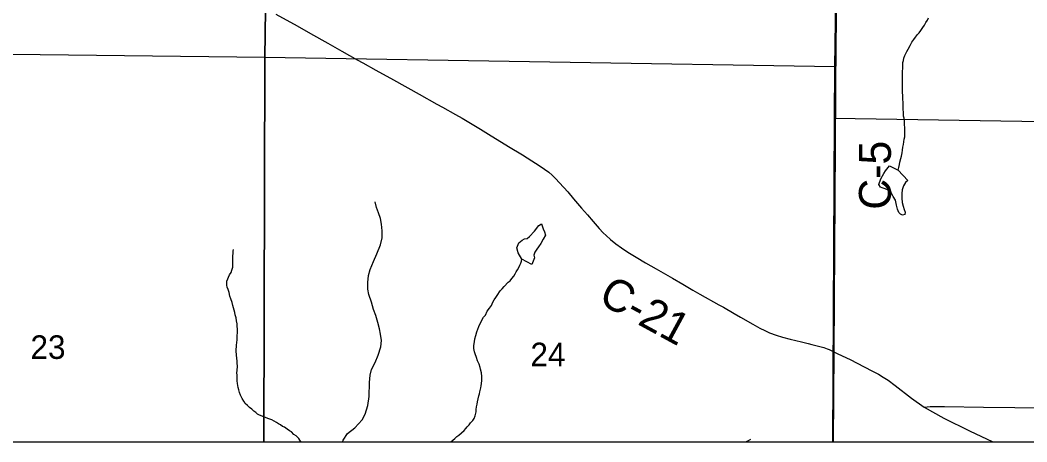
# Model space of a CAD drawing. Extents: x 0 to 34, y 0 to 22.
# Drawn here: x 26.305 to 27.199, y 13.436 to 13.811 of the extents above; entities that cross this region are included whole.
import ezdxf

# ---------------------------------------------------------------- set-up
doc = ezdxf.new("R2010")
doc.units = 0
for name, color, linetype in [('GM_X_County_Road', 7, 'Continuous'), ('GM_X_County_Road_Text', 7, 'Continuous'), ('GM_X_Minor_River', 7, 'Continuous'), ('GM_X_Section', 7, 'Continuous'), ('GM_X_Section_Text', 7, 'Continuous'), ('GM_X_Township_Road', 7, 'Continuous'), ('GM_X_Unincorporated', 7, 'Continuous'), ('SC_Scratch1', 7, 'Continuous'), ('SH_Border', 7, 'Continuous'), ('SH_Cut_Line', 7, 'Continuous')]:
    doc.layers.add(name, color=color, linetype=linetype)

msp = doc.modelspace()

# ---------------------------------------------------------------- linework, layer by layer
at = {"layer": 'GM_X_County_Road'}
for points in [[(27.02756, 13.43613), (27.02773, 13.45635), (27.02798, 13.49359), (27.02798, 13.51159), (27.0279, 13.51604), (27.02773, 13.52187), (27.02781, 13.53921), (27.02831, 13.58607), (27.02854, 13.627), (27.02896, 13.66909), (27.02939, 13.72226), (27.02962, 13.77184), (27.03013, 13.80886), (27.03053, 13.84985)], [(26.53202, 13.81591), (26.55073, 13.80543), (26.56264, 13.79873), (26.57808, 13.79005), (26.59053, 13.78305), (26.60409, 13.77547), (26.60925, 13.77261), (26.62091, 13.76611), (26.63641, 13.75753), (26.6592, 13.74482), (26.67496, 13.73609), (26.68014, 13.73326), (26.69155, 13.72694), (26.69751, 13.72357), (26.7137, 13.7137), (26.72085, 13.70932), (26.73861, 13.69847), (26.75107, 13.69086), (26.75955, 13.68567), (26.76585, 13.68165), (26.77074, 13.6783), (26.77448, 13.6755), (26.7776, 13.6729), (26.78053, 13.67008), (26.78416, 13.66622), (26.79132, 13.65804), (26.79661, 13.65194), (26.80373, 13.64372), (26.80901, 13.6376), (26.81407, 13.63173), (26.81938, 13.62567), (26.82298, 13.62184), (26.82561, 13.61923), (26.82928, 13.61591), (26.83409, 13.61203), (26.8391, 13.6084), (26.84478, 13.60463), (26.85218, 13.60007), (26.86047, 13.59518), (26.8653, 13.59237), (26.86987, 13.58972), (26.88444, 13.5814), (26.89358, 13.5761), (26.90269, 13.57076), (26.90892, 13.56728), (26.92575, 13.55793), (26.92981, 13.55564), (26.93925, 13.55023), (26.9449, 13.54697), (26.95594, 13.54062), (26.9622, 13.53721), (26.96663, 13.53499), (26.97083, 13.53305), (26.97662, 13.53088), (26.98222, 13.52913), (26.98911, 13.52732), (26.99909, 13.52496), (27.00514, 13.52353), (27.00846, 13.52271), (27.01538, 13.5209), (27.01896, 13.51979), (27.02202, 13.51867), (27.02388, 13.51798), (27.02624, 13.51688), (27.0279, 13.51604)], [(27.0279, 13.51604), (27.03143, 13.51432), (27.0423, 13.50921), (27.05493, 13.50283), (27.06238, 13.499), (27.06753, 13.49615), (27.07176, 13.49357), (27.07609, 13.49088), (27.0825, 13.48611), (27.09705, 13.47485), (27.10809, 13.46685), (27.12569, 13.45704), (27.14833, 13.44604), (27.16935, 13.43613)]]:
    msp.add_lwpolyline(points, dxfattribs=at)
at = {"layer": 'GM_X_Minor_River'}
for points in [[(27.08515, 13.67745), (27.08554, 13.6797), (27.08619, 13.68253), (27.08662, 13.68461), (27.08747, 13.68762), (27.08791, 13.68989), (27.08856, 13.69272), (27.08882, 13.69519), (27.08928, 13.69783), (27.08972, 13.70029), (27.08998, 13.70256), (27.09042, 13.70483), (27.09086, 13.70691), (27.0911, 13.71526), (27.09078, 13.71755), (27.0907, 13.72135), (27.09038, 13.72345), (27.08987, 13.72537), (27.08973, 13.72727), (27.0895, 13.7326), (27.08938, 13.73507), (27.08946, 13.73773), (27.08934, 13.7402), (27.08921, 13.74248), (27.08898, 13.74743), (27.08885, 13.74971), (27.08891, 13.7518), (27.08879, 13.75427), (27.08894, 13.75959), (27.08881, 13.76168), (27.08908, 13.77118), (27.08932, 13.77307), (27.08975, 13.77477), (27.09019, 13.77684), (27.09101, 13.7791), (27.09201, 13.78097), (27.09282, 13.78266), (27.09402, 13.78491), (27.09563, 13.78809), (27.09723, 13.79108), (27.09901, 13.79331), (27.1004, 13.79556), (27.10217, 13.79779), (27.10373, 13.79945), (27.10531, 13.8015), (27.1069, 13.80411), (27.10847, 13.80616), (27.10968, 13.8084), (27.11125, 13.81045), (27.11207, 13.81252)], [(27.07615, 13.65956), (27.07353, 13.66078), (27.0709, 13.66162), (27.06941, 13.66242), (27.06795, 13.66456), (27.06962, 13.66963), (27.07224, 13.67449), (27.07382, 13.67672), (27.07737, 13.68117), (27.08515, 13.67745)], [(27.08515, 13.67745), (27.09368, 13.66834), (27.09172, 13.66631), (27.08974, 13.66352), (27.08849, 13.65976), (27.0884, 13.65673), (27.08847, 13.65255), (27.08873, 13.64855), (27.08939, 13.64531), (27.09044, 13.64243), (27.09132, 13.64012), (27.09088, 13.63804), (27.08878, 13.63754), (27.08709, 13.63816), (27.08562, 13.63972), (27.08437, 13.64261), (27.08353, 13.64624), (27.08272, 13.65063), (27.08054, 13.65411), (27.07874, 13.6574), (27.07615, 13.65956)], [(26.59122, 13.43613), (26.59177, 13.43763), (26.59555, 13.4434), (26.60215, 13.44852), (26.60863, 13.45555), (26.61144, 13.46078), (26.61357, 13.4685), (26.61475, 13.47644), (26.61512, 13.48877), (26.61588, 13.4952), (26.61699, 13.5003), (26.62021, 13.50647), (26.62287, 13.51304), (26.62518, 13.52037), (26.62572, 13.52605), (26.62495, 13.53177), (26.62395, 13.53655), (26.6226, 13.5421), (26.6207, 13.54823), (26.61858, 13.55361), (26.61688, 13.56011), (26.61462, 13.56702), (26.61381, 13.57179), (26.6136, 13.57749), (26.61437, 13.58392), (26.61585, 13.5892), (26.61872, 13.59633), (26.62177, 13.60307), (26.62485, 13.61095), (26.62656, 13.61736), (26.62655, 13.62344), (26.62597, 13.62953), (26.62498, 13.63431), (26.62305, 13.63949), (26.62148, 13.64428), (26.62012, 13.64926)], [(26.75065, 13.59846), (26.7474, 13.60407), (26.7462, 13.60828), (26.74785, 13.61298), (26.75077, 13.61536), (26.75289, 13.61643), (26.75517, 13.61656), (26.7575, 13.61839), (26.76182, 13.62319), (26.76577, 13.6282), (26.7679, 13.62985), (26.76966, 13.62524), (26.77073, 13.62274), (26.77158, 13.61967), (26.76939, 13.61613), (26.76737, 13.6122), (26.76539, 13.60922), (26.764, 13.60718), (26.76221, 13.60457), (26.76118, 13.60176), (26.76168, 13.59946), (26.75942, 13.59364)], [(26.55433, 13.43613), (26.55426, 13.43628), (26.55245, 13.43918), (26.55004, 13.44134), (26.5478, 13.44273), (26.54578, 13.44488), (26.54391, 13.44588), (26.54206, 13.44745), (26.53964, 13.44904), (26.53795, 13.44985), (26.5361, 13.45123), (26.53441, 13.45204), (26.53236, 13.45342), (26.52826, 13.45582), (26.52487, 13.45686), (26.52281, 13.45768), (26.52112, 13.4583), (26.51737, 13.45993), (26.51569, 13.46073), (26.51402, 13.46211), (26.51234, 13.4633), (26.5105, 13.46506), (26.50845, 13.46664), (26.5068, 13.46839), (26.50457, 13.47017), (26.50349, 13.4721), (26.50204, 13.47461), (26.50061, 13.47769), (26.49973, 13.47999), (26.49903, 13.48229), (26.49853, 13.4844), (26.49786, 13.48783), (26.49755, 13.49031), (26.49761, 13.49221), (26.49751, 13.49525), (26.49737, 13.49735), (26.49762, 13.49943), (26.49774, 13.50342), (26.49762, 13.50589), (26.49749, 13.50817), (26.49717, 13.51008), (26.49688, 13.51332), (26.49678, 13.51655), (26.49694, 13.52225), (26.49719, 13.52414), (26.49746, 13.52698), (26.49754, 13.53002), (26.49784, 13.53362), (26.49772, 13.53629), (26.4976, 13.53876), (26.49747, 13.54085), (26.49698, 13.54353), (26.49668, 13.54638), (26.4958, 13.54888), (26.49548, 13.55098), (26.49497, 13.55308), (26.49427, 13.55519), (26.49376, 13.55711), (26.49308, 13.55979), (26.49203, 13.56304), (26.49115, 13.56535), (26.49029, 13.5686), (26.48942, 13.57148), (26.48873, 13.57359), (26.48839, 13.57531), (26.48825, 13.57702), (26.4885, 13.57891), (26.48912, 13.5808), (26.48993, 13.58248), (26.49074, 13.58436), (26.49213, 13.5866), (26.49294, 13.58848), (26.49359, 13.59112), (26.49376, 13.59738), (26.49381, 13.59909), (26.49399, 13.60536), (26.49423, 13.60706)], [(26.6993, 13.44625), (26.70067, 13.44792), (26.70205, 13.44959), (26.70361, 13.45126), (26.70499, 13.45293), (26.70694, 13.45496), (26.70813, 13.45683), (26.70915, 13.45927), (26.71001, 13.46267), (26.71006, 13.46476), (26.71032, 13.46722), (26.71077, 13.46949), (26.71102, 13.47176), (26.71166, 13.47421), (26.71231, 13.47685), (26.71293, 13.47874), (26.71336, 13.48062), (26.71422, 13.48402), (26.71445, 13.48572), (26.7147, 13.48781), (26.71497, 13.49065), (26.71507, 13.49406), (26.71479, 13.49749), (26.71393, 13.50056), (26.7136, 13.50228), (26.71254, 13.50515), (26.71129, 13.50804), (26.71024, 13.51092), (26.709, 13.51419), (26.70848, 13.51591), (26.708, 13.51896), (26.70789, 13.52182), (26.70836, 13.52484), (26.70881, 13.52768), (26.70966, 13.5307), (26.7107, 13.5339), (26.71234, 13.53841), (26.71316, 13.54048), (26.71657, 13.54684), (26.71814, 13.5487), (26.71976, 13.55226), (26.72173, 13.55486), (26.7235, 13.55728), (26.72491, 13.5601), (26.72592, 13.56216), (26.72731, 13.56421), (26.7285, 13.56607), (26.73127, 13.57018), (26.73322, 13.57202), (26.73479, 13.57406), (26.73831, 13.57777), (26.74006, 13.57924), (26.74182, 13.58109), (26.74359, 13.58313), (26.7446, 13.58519), (26.7456, 13.58706), (26.74679, 13.58893), (26.74799, 13.59098), (26.7488, 13.59305), (26.74961, 13.59474), (26.75023, 13.59662), (26.75065, 13.59846)], [(26.75942, 13.59364), (26.75065, 13.59846)], [(26.68745, 13.43613), (26.68919, 13.43761), (26.69112, 13.43907), (26.69288, 13.44073), (26.69463, 13.4422), (26.6993, 13.44625)], [(26.94975, 13.43613), (26.94981, 13.43615), (26.95212, 13.43723), (26.95405, 13.4385)]]:
    msp.add_lwpolyline(points, dxfattribs=at)
at = {"layer": 'GM_X_Section'}
for points in [[(26.02249, 14.29244), (26.5292, 14.28703), (26.52223, 13.77736), (26.02278, 13.78319)], [(26.5292, 14.28703), (27.03605, 14.26997), (27.02872, 13.76918), (26.52223, 13.77736)], [(27.03605, 14.26997), (27.53348, 14.26354), (27.52771, 13.71514), (27.02861, 13.72334), (27.02872, 13.76918)]]:
    msp.add_lwpolyline(points, close=True, dxfattribs=at)
at = {"layer": 'GM_X_Township_Road'}
msp.add_lwpolyline([(27.10809, 13.46685), (27.11352, 13.46739), (27.11689, 13.46764), (27.12638, 13.46744), (27.16087, 13.46693), (27.1888, 13.46657), (27.23395, 13.46616)], dxfattribs=at)
at = {"layer": 'GM_X_Unincorporated'}
for points in [[(26.02252, 13.43613), (26.52131, 13.43613), (26.52223, 13.77736), (26.02278, 13.78319)], [(26.52131, 13.43613), (27.0269, 13.43613), (27.02861, 13.72334), (27.02872, 13.76918), (26.52223, 13.77736)], [(27.0269, 13.43613), (27.52733, 13.43613), (27.52771, 13.71514), (27.02861, 13.72334)]]:
    msp.add_lwpolyline(points, close=True, dxfattribs=at)
at = {"layer": 'SC_Scratch1'}
msp.add_line((1.5, 13.43613), (32, 13.43613), dxfattribs=at)
for points in [[(27.20951, 15.31337), (27.19288, 15.31357), (27.17131, 15.31384), (27.1244, 15.3146), (27.11011, 15.31474), (27.09831, 15.31485), (27.08868, 15.31488), (27.06227, 15.315), (27.04578, 15.31508), (27.04576, 15.31247), (27.03971, 14.68583), (27.03558, 14.26819), (27.03207, 14.16936), (27.02867, 13.6522), (27.02778, 13.51631), (27.02715, 13.43613), (30.0382, 13.43613)], [(24.06692, 13.43613), (27.02715, 13.43613), (27.02778, 13.51631), (27.02867, 13.6522), (27.03207, 14.16936), (27.03558, 14.26819), (27.03971, 14.68583)]]:
    msp.add_lwpolyline(points, dxfattribs=at)
at = {"layer": 'SH_Border'}
msp.add_lwpolyline([(23.89999, 20.23613), (23.89999, 13.43613), (30.69999, 13.43613), (30.69999, 20.23613)], close=True, dxfattribs=at)
at = {"layer": 'SH_Cut_Line'}
msp.add_lwpolyline([(23.89999, 20.23613), (23.89999, 13.43613), (30.0382, 13.43613)], dxfattribs=at)

# ---------------------------------------------------------------- texts
at = {"layer": 'GM_X_County_Road_Text'}
for s, rotation, p in [('C-5', 90, (27.07861, 13.64225)), ('C-21', 331.44411, (26.81732, 13.56014))]:
    msp.add_text(s, height=0.028409, rotation=rotation, dxfattribs=at).set_placement(p)
at = {"layer": 'GM_X_Section_Text'}
for s, p in [('23', (26.31383, 13.50978)), ('24', (26.75821, 13.50327))]:
    msp.add_text(s, height=0.020928, rotation=0.00001, dxfattribs=at).set_placement(p)

doc.saveas('drawing.dxf')
